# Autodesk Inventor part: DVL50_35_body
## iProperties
Created: 2009-07
Part Number: DVL50_35_body
Document SubType Name: Modeling
Designer: TB
Mass: 338.111 g
Surface Area: 917.827 cm^2
Volume: 338.111 cm^3
Density: 1 g/cm^3
Author: TB
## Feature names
1. Kropp [Revolution]
2. Chamfer
3. Extrusion2
4. Hole1
5. Revolution2
6. Hole2
7. Fillet1
